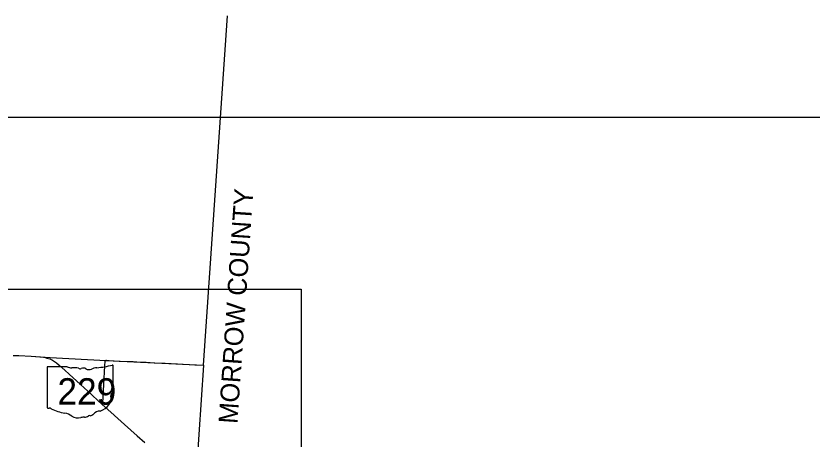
# Model space of a CAD drawing. Extents: x 1729596 to 1925846, y 659247 to 911751.
# Drawn here: x 1813555 to 1855559, y 883019 to 905333 of the extents above; entities that cross this region are included whole.
import ezdxf

# ---------------------------------------------------------------- set-up
doc = ezdxf.new("R2010")
doc.units = 0
for name, color, linetype in [('GM_X_Adjacent_County', 7, 'Continuous'), ('GM_X_Adjacent_County_Text', 7, 'Continuous'), ('GM_X_County', 7, 'Continuous'), ('GM_X_State_Route', 7, 'Continuous'), ('GM_X_State_Shield', 7, 'Continuous'), ('GM_X_Township_Road', 7, 'Continuous'), ('SC_Scratch1', 7, 'Continuous'), ('SH_Data', 7, 'Continuous')]:
    doc.layers.add(name, color=color, linetype=linetype)

msp = doc.modelspace()

# ---------------------------------------------------------------- linework, layer by layer
at = {"layer": 'GM_X_Adjacent_County'}
msp.add_line((1823458, 886911), (1824723, 905333), dxfattribs=at)
at = {"layer": 'GM_X_County'}
msp.add_lwpolyline([(1813443, 887429), (1813717, 887422), (1814360, 887388), (1814847, 887358), (1815353, 887328), (1818316, 887169), (1823458, 886911), (1823082, 881429), (1826517, 881205), (1828513, 881052), (1829123, 881005), (1835395, 880574), (1836682, 880495), (1836708, 880754), (1839410, 880574), (1842150, 880416), (1845959, 880135), (1850147, 879854), (1850017, 877290), (1849634, 872258), (1849106, 864311), (1848864, 860810), (1848787, 859601)], dxfattribs=at)
at = {"layer": 'GM_X_State_Route'}
for points in [[(1813408, 887426), (1813443, 887429), (1813717, 887422), (1814360, 887388), (1814824, 887360)], [(1814824, 887360), (1814847, 887358), (1815015, 887333), (1815089, 887321), (1815189, 887294), (1815338, 887242), (1815486, 887171), (1815704, 887032), (1815841, 886918), (1816128, 886656), (1816355, 886449), (1816954, 885901), (1817356, 885538), (1818106, 884845), (1818568, 884430), (1818934, 884102), (1819283, 883790), (1819954, 883190), (1820355, 882842)]]:
    msp.add_lwpolyline(points, dxfattribs=at)
at = {"layer": 'GM_X_State_Shield'}
for p, q in [((1815205, 886800), (1815205, 884687)), ((1815205, 886800), (1815205, 884687)), ((1816258, 886837), (1815239, 886837)), ((1816258, 886837), (1815239, 886837)), ((1818685, 885784), (1818685, 886889)), ((1818685, 885784), (1818685, 886889)), ((1818685, 885784), (1818685, 885784)), ((1818685, 885784), (1818685, 885784))]:
    msp.add_line(p, q, dxfattribs=at)
for centre, major_axis, start_param, end_param in [((1815244, 886805), (40.3, 0), 1.712693, 3.28349), ((1815244, 886805), (40.3, 0), 1.712693, 3.28349), ((1816501, 887082), (391, 0), 4.042523, 4.731795), ((1816501, 887082), (391, 0), 4.042523, 4.731795), ((1816630, 885650), (1404, 0), 1.404758, 1.657858), ((1816630, 885650), (1404, 0), 1.404758, 1.657858), ((1816949, 886816), (113, 0), 3.836095, 5.185415), ((1816949, 886816), (113, 0), 3.836095, 5.185415), ((1817115, 886572), (235, 0), 0.950623, 2.079405), ((1817115, 886572), (235, 0), 0.950623, 2.079405), ((1817418, 886907), (282, 0), 4.081561, 5.145723), ((1817418, 886907), (282, 0), 4.081561, 5.145723), ((1817916, 886191), (743, 0), 1.699011, 2.107814), ((1817916, 886191), (743, 0), 1.699011, 2.107814), ((1817445, 889718), (3691, 0), 4.814394, 5.042369), ((1817445, 889718), (3691, 0), 4.814394, 5.042369), ((1818646, 886894), (38.7, 0), 6.141152, 7.989035), ((1818646, 886894), (38.7, 0), 6.141152, 7.989035), ((1818824, 885321), (262, 0), 2.387724, 3.262537), ((1818824, 885321), (262, 0), 2.387724, 3.262537), ((1818676, 885703), (60, 0), 1.883978, 3.671073), ((1818676, 885703), (60, 0), 1.883978, 3.671073), ((1818295, 885563), (360, 0), 5.934695, 6.695948), ((1818295, 885563), (360, 0), 5.934695, 6.695948), ((1818644, 885779), (41.5, 0), 5.05454, 6.418171), ((1818644, 885779), (41.5, 0), 5.05454, 6.418171), ((1817652, 885180), (923, 0), 5.101752, 6.440018), ((1817652, 885180), (923, 0), 5.101752, 6.440018), ((1815245, 884683), (40.7, 0), 3.00124, 4.508301), ((1815245, 884683), (40.7, 0), 3.00124, 4.508301), ((1815251, 884899), (310, 0), 4.665946, 4.897461), ((1815251, 884899), (310, 0), 4.665946, 4.897461), ((1815314, 884565), (112, 0), 0.519207, 1.627899), ((1815314, 884565), (112, 0), 0.519207, 1.627899), ((1816728, 886464), (2665, 0), 4.195997, 4.488961), ((1816728, 886464), (2665, 0), 4.195997, 4.488961), ((1815933, 883738), (834, 0), 0.823519, 1.323587), ((1815933, 883738), (834, 0), 0.823519, 1.323587), ((1816835, 884555), (529, 0), 4.026481, 4.996735), ((1816835, 884555), (529, 0), 4.026481, 4.996735), ((1817179, 884397), (282, 0), 4.691044, 5.507374), ((1817179, 884397), (282, 0), 4.691044, 5.507374), ((1817434, 884192), (79.4, 0), 1.147584, 2.315152), ((1817434, 884192), (79.4, 0), 1.147584, 2.315152), ((1817401, 884482), (298, 0), 4.937069, 5.64225), ((1817401, 884482), (298, 0), 4.937069, 5.64225), ((1818041, 884094), (506, 0), 1.647645, 2.488434), ((1818041, 884094), (506, 0), 1.647645, 2.488434), ((1817141, 883824), (435, 0), 1.495662, 1.94098), ((1817141, 883824), (435, 0), 1.495662, 1.94098)]:
    msp.add_ellipse(centre, major_axis=major_axis, ratio=0.8, start_param=start_param, end_param=end_param, dxfattribs=at)
at = {"layer": 'GM_X_Township_Road'}
for points in [[(1818106, 884845), (1818121, 884859), (1818133, 884883), (1818136, 884905), (1818252, 886879), (1818267, 887127), (1818268, 887136), (1818271, 887143), (1818274, 887150), (1818280, 887162)], [(1818280, 887162), (1818283, 887165), (1818289, 887169), (1818299, 887170), (1818316, 887171), (1818334, 887171), (1818481, 887161), (1819006, 887135), (1819514, 887112), (1819744, 887102), (1820121, 887082), (1820432, 887068), (1820842, 887046), (1821432, 887018), (1822088, 886984), (1822989, 886935), (1823461, 886911)]]:
    msp.add_lwpolyline(points, dxfattribs=at)
at = {"layer": 'SC_Scratch1'}
msp.add_lwpolyline([(1729596, 899996), (1925846, 899996), (1925846, 765496), (1729596, 765496)], close=True, dxfattribs=at)
at = {"layer": 'SH_Data'}
for p, q in [((1752099, 890928), (1828599, 890928)), ((1828599, 890928), (1828599, 814428))]:
    msp.add_line(p, q, dxfattribs=at)

# ---------------------------------------------------------------- texts
at = {"layer": 'GM_X_Adjacent_County_Text'}
msp.add_text('MORROW COUNTY', height=1000, rotation=86.0902, dxfattribs=at).set_placement((1825240, 883804))
at = {"layer": 'GM_X_State_Shield'}
msp.add_text('229', height=1392.2, dxfattribs=at).set_placement((1815744, 884836))
msp.add_text('229', height=1392.2, dxfattribs=at).set_placement((1815744, 884836))

doc.saveas('drawing.dxf')
